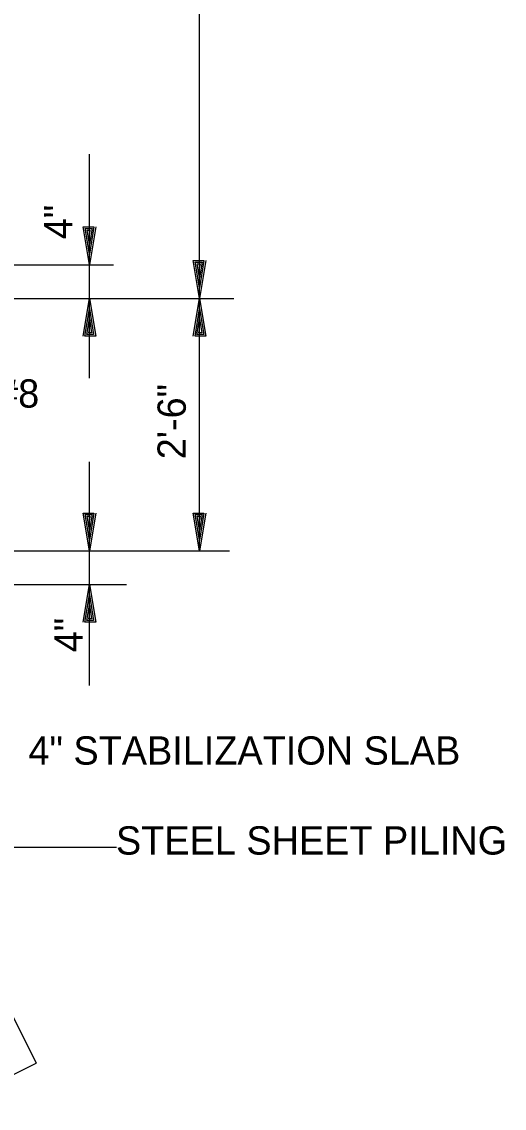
# Model space of a CAD drawing. Extents: x 6 to 106, y 3 to 74.
# Drawn here: x 96.9 to 103.27, y 48.94 to 63.29 of the extents above; entities that cross this region are included whole.
import ezdxf

# ---------------------------------------------------------------- set-up
doc = ezdxf.new("R2010")
doc.units = 0
doc.layers.add('Level 22', color=7, linetype='Continuous')
doc.layers.add('Level 50', color=7, linetype='Continuous')

msp = doc.modelspace()

# ---------------------------------------------------------------- linework, layer by layer
at = {"layer": 'Level 22'}
for p, q in [((99.246, 59.641), (99.246, 68.974)), ((97.793, 60.085), (97.793, 61.544)), ((87.475, 60.085), (98.111, 60.085)), ((97.793, 59.641), (97.793, 60.085)), ((95.251, 59.641), (99.7, 59.641)), ((97.793, 58.586), (97.793, 59.641)), ((99.246, 56.307), (99.246, 59.641)), ((97.793, 56.307), (97.793, 57.482)), ((95.297, 56.307), (99.643, 56.307)), ((97.793, 55.863), (97.793, 56.307)), ((95.342, 55.863), (98.283, 55.863)), ((97.793, 54.529), (97.793, 55.863)), ((96.599, 52.392), (98.151, 52.392)), ((96.329, 51.063), (97.09, 49.541)), ((95.898, 48.944), (97.09, 49.541))]:
    msp.add_line(p, q, dxfattribs=at)
at = {"layer": 'Level 50'}
for p, q in [((97.793, 60.224), (97.793, 60.224)), ((97.793, 60.085), (97.793, 60.085)), ((99.246, 59.779), (99.246, 59.779)), ((97.793, 59.641), (97.793, 59.641)), ((99.246, 59.641), (99.246, 59.641)), ((99.246, 59.641), (99.246, 59.641)), ((97.793, 59.502), (97.793, 59.502)), ((99.246, 59.502), (99.246, 59.502)), ((97.793, 56.446), (97.793, 56.446)), ((99.246, 56.446), (99.246, 56.446)), ((97.793, 56.307), (97.793, 56.307)), ((99.246, 56.307), (99.246, 56.307)), ((97.793, 55.863), (97.793, 55.863)), ((97.793, 55.724), (97.793, 55.724))]:
    msp.add_line(p, q, dxfattribs=at)
for points in [[(97.876, 60.584), (97.793, 60.085), (97.711, 60.584), (97.852, 60.584), (97.793, 60.224), (97.737, 60.562), (97.828, 60.562), (97.793, 60.357), (97.764, 60.541), (97.801, 60.541), (97.793, 60.496)], [(99.328, 60.139), (99.246, 59.641), (99.163, 60.139), (99.304, 60.139), (99.246, 59.779), (99.19, 60.118), (99.28, 60.118), (99.246, 59.913), (99.216, 60.097), (99.254, 60.097), (99.246, 60.051)], [(97.711, 59.142), (97.793, 59.641), (97.876, 59.142), (97.735, 59.142), (97.793, 59.502), (97.849, 59.163), (97.759, 59.163), (97.793, 59.369), (97.823, 59.185), (97.785, 59.185), (97.793, 59.23)], [(99.163, 59.142), (99.246, 59.641), (99.328, 59.142), (99.187, 59.142), (99.246, 59.502), (99.302, 59.163), (99.211, 59.163), (99.246, 59.369), (99.275, 59.185), (99.238, 59.185), (99.246, 59.23)], [(97.876, 56.806), (97.793, 56.307), (97.711, 56.806), (97.852, 56.806), (97.793, 56.446), (97.737, 56.785), (97.828, 56.785), (97.793, 56.579), (97.764, 56.763), (97.801, 56.763), (97.793, 56.718)], [(99.328, 56.806), (99.246, 56.307), (99.163, 56.806), (99.304, 56.806), (99.246, 56.446), (99.19, 56.785), (99.28, 56.785), (99.246, 56.579), (99.216, 56.763), (99.254, 56.763), (99.246, 56.718)], [(97.711, 55.364), (97.793, 55.863), (97.876, 55.364), (97.735, 55.364), (97.793, 55.724), (97.849, 55.386), (97.759, 55.386), (97.793, 55.591), (97.823, 55.407), (97.785, 55.407), (97.793, 55.452)]]:
    msp.add_lwpolyline(points, dxfattribs=at)

# ---------------------------------------------------------------- texts
at = {"layer": 'Level 22'}
for s, p in [('4"', (97.569, 60.422)), ('2\'-6"', (99.065, 57.516)), ('4"', (97.705, 54.967))]:
    msp.add_text(s, height=0.3733, rotation=90, dxfattribs=at).set_placement(p)
for s, height, p in [('10 #8', 0.3733, (95.882, 58.198)), ('4" STABILIZATION SLAB', 0.37333, (96.989, 53.483)), ('STEEL SHEET PILING', 0.37333, (98.144, 52.295))]:
    msp.add_text(s, height=height, dxfattribs=at).set_placement(p)

doc.saveas('drawing.dxf')
